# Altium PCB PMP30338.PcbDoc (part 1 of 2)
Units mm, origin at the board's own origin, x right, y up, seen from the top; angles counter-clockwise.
Board outline 50.04 x 70.1 mm, 4 copper layers (Top Layer, GND, Signal Layer, Bottom Layer), stack 2.028 mm thick; 61 components, 55 nets, 302 pads, 122 vias.
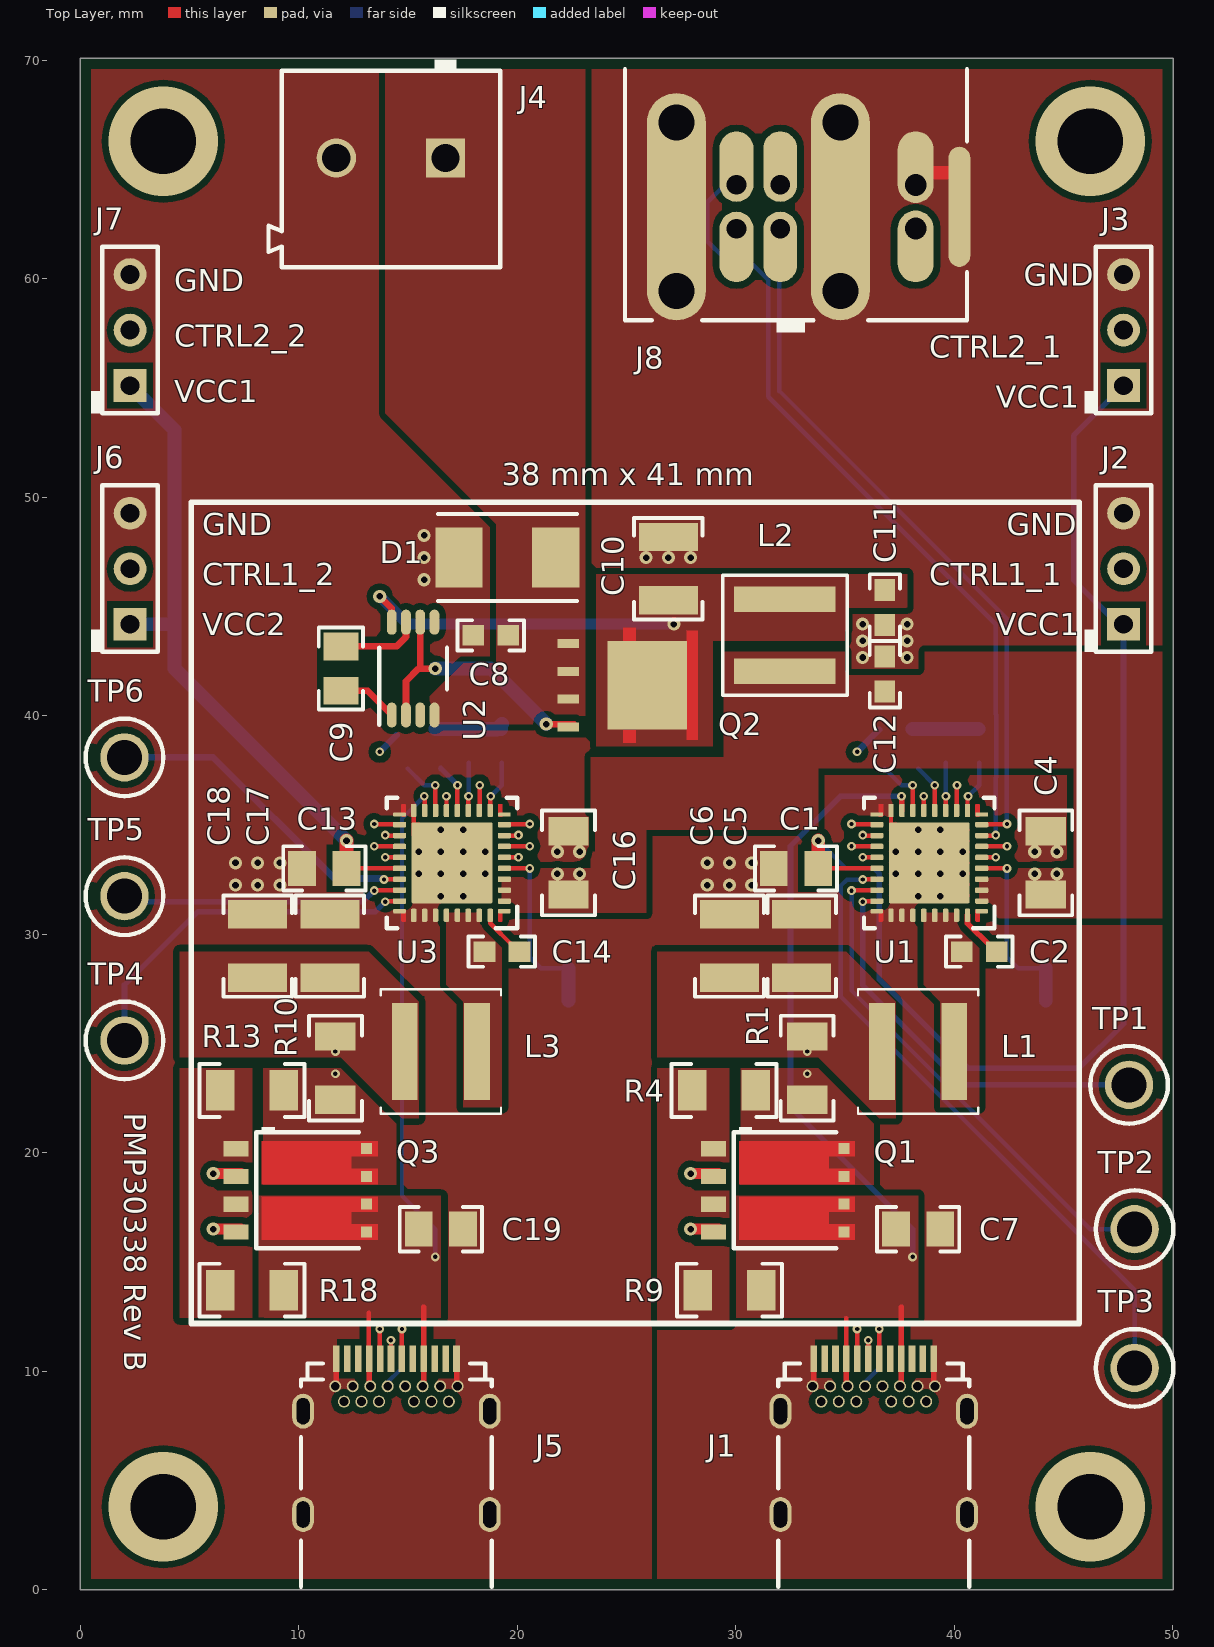
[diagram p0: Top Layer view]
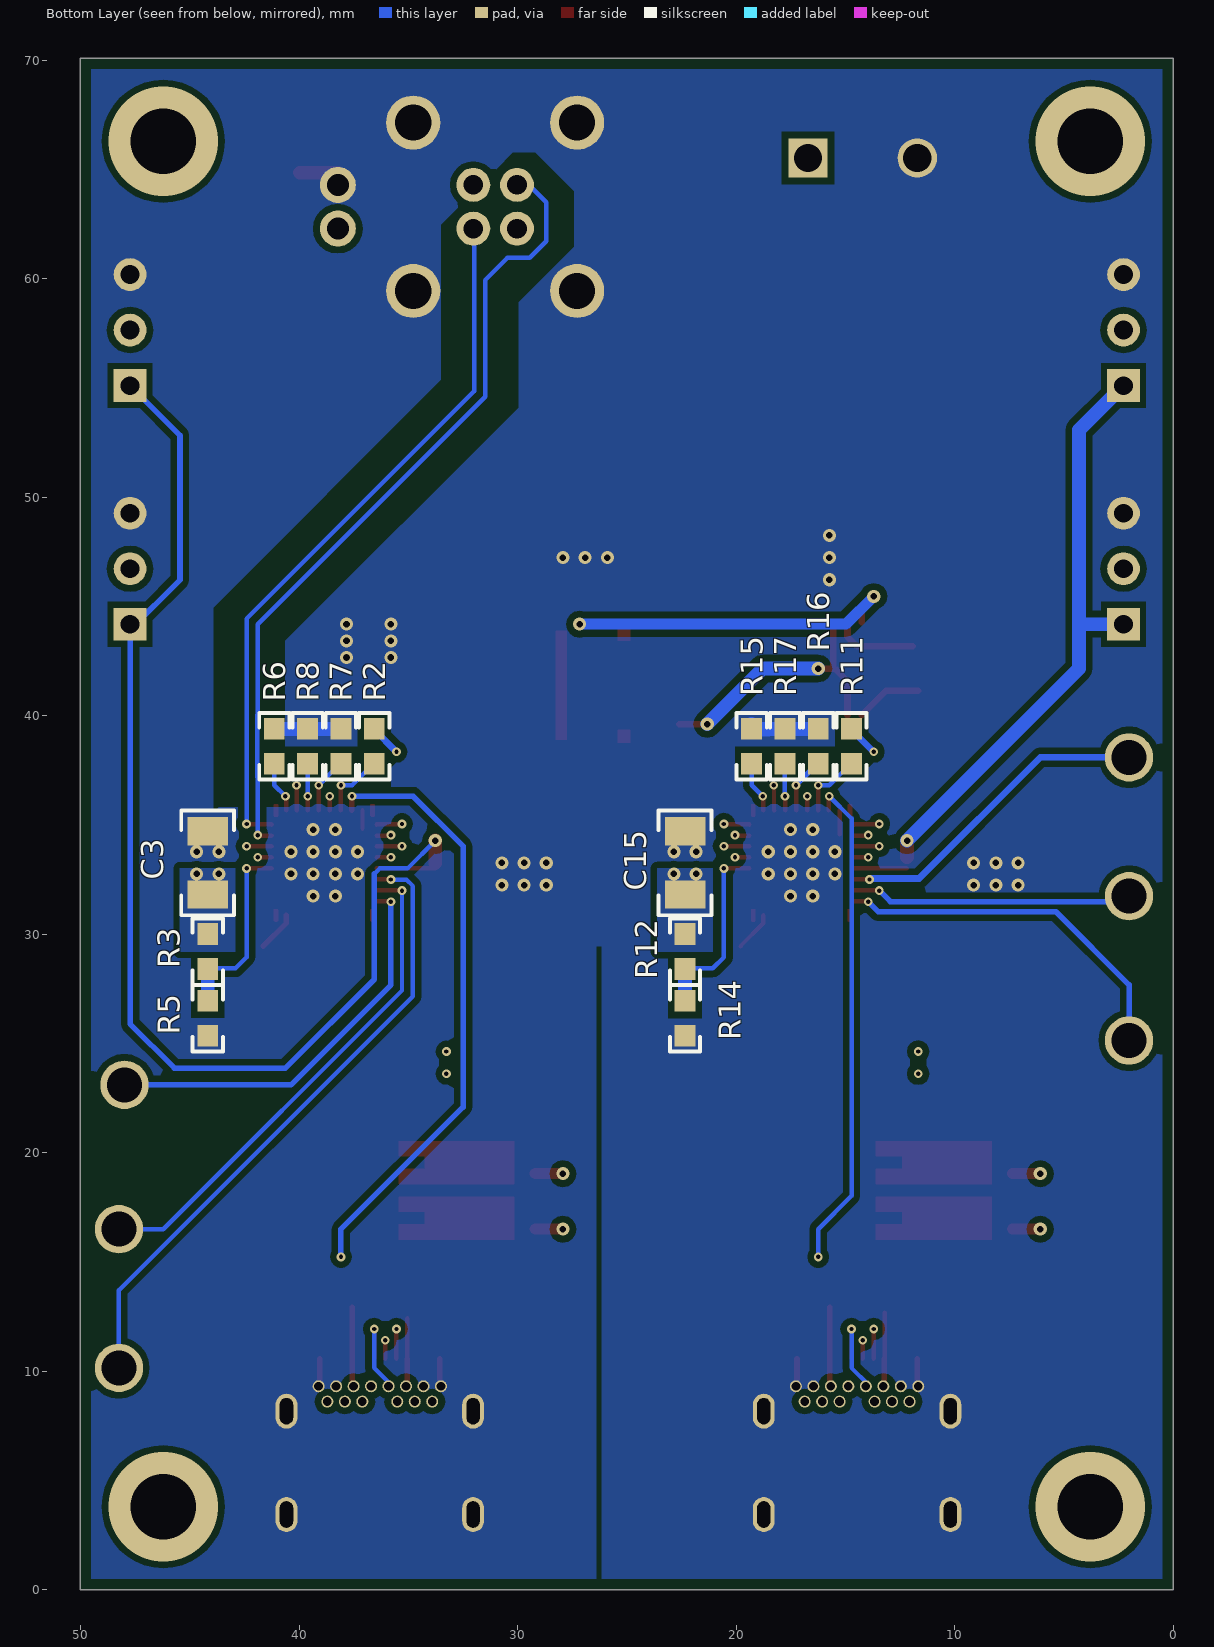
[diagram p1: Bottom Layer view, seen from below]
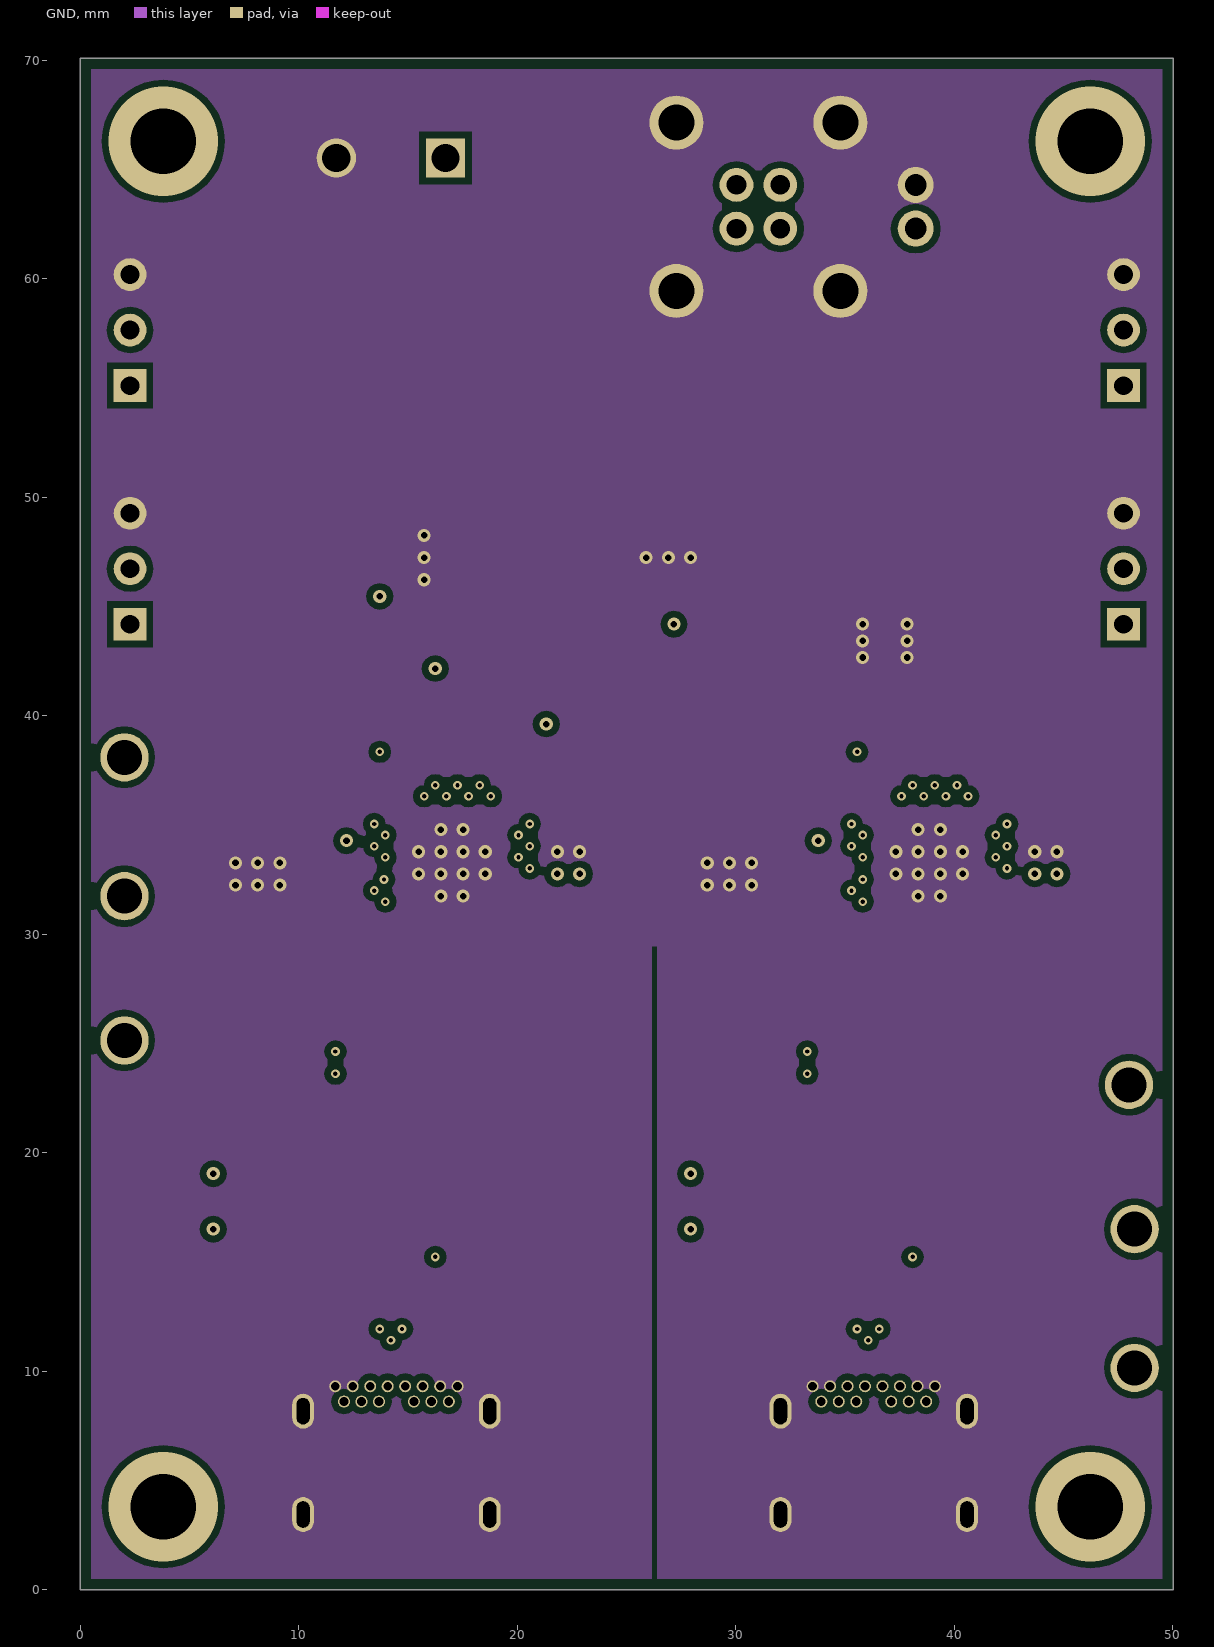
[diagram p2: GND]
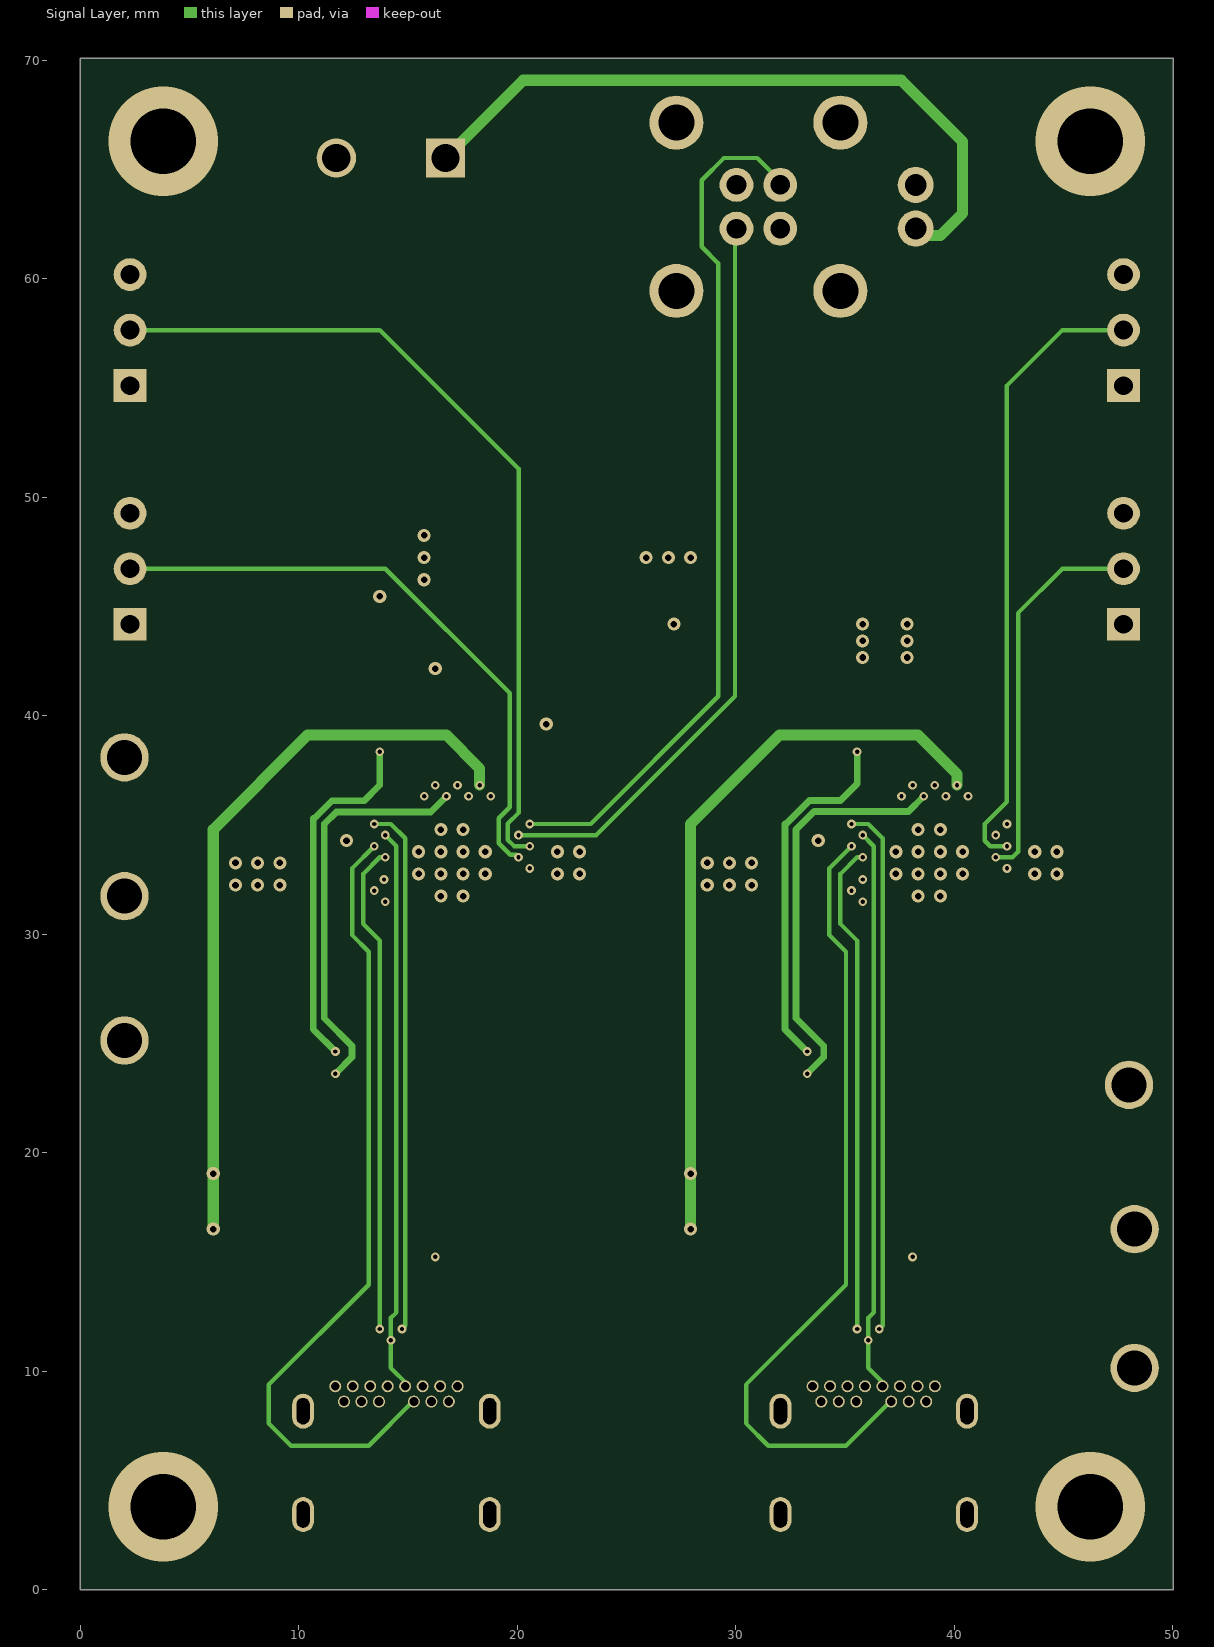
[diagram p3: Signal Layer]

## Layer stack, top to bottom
Top Solder: solder mask 0.0102, Solder Resist, Dk 3.5
Top Layer: signal copper 0.0356
Dielectric1: core 1.5037, FR-4, Dk 4.8
GND: signal copper 0.036
Dielectric 3: prepreg 0.127, Dk 4.2
Signal Layer: signal copper 0.036
Dielectric 2: core 0.254, Dk 4.2
Bottom Layer: signal copper 0.0356
Bottom Solder: solder mask 0.0102, Solder Resist, Dk 3.5

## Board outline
0,0 0,70.104 50.038,70.104 50.038,0

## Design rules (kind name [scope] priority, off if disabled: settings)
AcuteAngle [All] p1: minimum=4.50000000000000E+0001 checktracksonly=FALSE
AssemblyTestPointUsage [All] p1: valid=2
Clearance Clearance_Keepouts [((IsTrack Or IsArc) And Not InPoly) And IsFree and IsKeepOut vs ((IsTrack Or IsArc) And Not InPoly) And IsFree and IsKeepOut] p1: gap=0 ignorepadtopadclearanceinfootprint=FALSE
Clearance Clearance_BoardEdge_MountingHoles [OnCopper and InComponentClass('Mounting Holes') vs IsKeepOut] p2: gap=1.016 ignorepadtopadclearanceinfootprint=FALSE except(0: Arc-Hole Track-Hole SMDPad-Hole THPad-Hole Via-Hole Fill-Hole Poly-Hole Region-Hole Text-Hole)
Clearance Clearance_BoardEdge_Poly [OnCopper and InPoly vs IsKeepOut] p3: gap=0.635 ignorepadtopadclearanceinfootprint=FALSE except(0: Arc-Hole Track-Hole SMDPad-Hole THPad-Hole Via-Hole Fill-Hole Poly-Hole Region-Hole Text-Hole)
Clearance Clearance_BoardEdge [OnCopper and Not InComponentClass('Logo') and not InComponentClass('FiducialMark') and not InRegion(1000,500,4000,800) and Not IsKeepout vs IsKeepOut] p4: gap=1.905 ignorepadtopadclearanceinfootprint=FALSE except(0: Arc-Hole Track-Hole SMDPad-Hole THPad-Hole Via-Hole Fill-Hole Poly-Hole Region-Hole Text-Hole)
Clearance Clearance_Poly [InPolygon] p5: gap=0.3 ignorepadtopadclearanceinfootprint=FALSE
Clearance [All] p6: gap=0.2 ignorepadtopadclearanceinfootprint=FALSE except(0: Arc-Hole Track-Hole SMDPad-Hole THPad-Hole Via-Hole Fill-Hole Poly-Hole Region-Hole Text-Hole)
ComponentClearance ComponentClearance_MountingHoles_FiducialMarks [InComponentClass('Mounting Holes') vs InComponentClass('FiducialMark')] p1: gap=1.27 collisioncheckmode=3 verticalgap=0.254 showdistances=FALSE
ComponentClearance ComponentClearance_Shunt [InComponentClass('Header') vs InComponentClass('Shunt')] p2: gap=0 collisioncheckmode=3 verticalgap=0 showdistances=FALSE
ComponentClearance ComponentClearance_Logo [InComponentClass('Logo')] p3: gap=1.27 collisioncheckmode=3 verticalgap=0.254 showdistances=FALSE
ComponentClearance ComponentClearance_ScrewToNut [(HasFootprint('NY PMS 440 0025 PH')) vs (HasFootprint('Keystone_1902C'))] p4: gap=0.127 collisioncheckmode=3 verticalgap=0.254 showdistances=FALSE
ComponentClearance ComponentClearance_MountingHoles [InComponentClass('Mounting Holes')] p5: gap=6.35 collisioncheckmode=3 verticalgap=2540 showdistances=FALSE
ComponentClearance ComponentClearance_SmallPassives [HasFootprint('0201*') or HasFootprint('0402*') or HasFootprint('0508') or HasFootprint('0603*') or HasFootprint('0612') or HasFootprint('0805*') or HasFootprint('0815*') or HasFootprint('0830*') or HasFootprint('1206*') or HasFootprint('1210*') or HasFootprint('1808*') or HasFootprint('1812*') or HasFootprint('1825*') or HasFootprint('2010*') or HasFootprint('2220*') or HasFootprint('2225*') or HasFootprint('2512*') or HasFootprint('2728*') or HasFootprint('3518*') vs HasFootprint('0201*') or HasFootprint('0402*') or HasFootprint('0508') or HasFootprint('0603*') or HasFootprint('0612') or HasFootprint('0805*') or HasFootprint('0815*') or HasFootprint('0830*') or HasFootprint('1206*') or HasFootprint('1210*') or HasFootprint('1808*') or HasFootprint('1812*') or HasFootprint('1825*') or HasFootprint('2010*') or HasFootprint('2220*') or HasFootprint('2225*') or HasFootprint('2512*') or HasFootprint('2728*') or HasFootprint('3518*')] p6: gap=0.508 collisioncheckmode=3 verticalgap=0.254 showdistances=FALSE
ComponentClearance ComponentClearance_THtoSMT [IsThruComponent vs IsSMTComponent] p7: gap=2.54 collisioncheckmode=3 verticalgap=0.762 showdistances=FALSE
ComponentClearance ComponentClearance_THtoTH [IsThruComponent vs IsThruComponent] p8: gap=3 collisioncheckmode=3 verticalgap=0.762 showdistances=FALSE
ComponentClearance [All] p9: gap=1.016 collisioncheckmode=3 verticalgap=0.254 showdistances=FALSE
DiffPairsRouting [All] p1: maxlimit=2.54 minlimit=0.254 mostfreqgap=0.254 toplayer_minwidth=0.381 toplayer_maxwidth=0.381 toplayer_prefwidth=0.381 midlayer1_minwidth=0.381 midlayer1_maxwidth=0.381 midlayer1_prefwidth=0.381 midlayer2_minwidth=0.381 midlayer2_maxwidth=0.381 midlayer2_prefwidth=0.381 bottomlayer_minwidth=0.381 bottomlayer_maxwidth=0.381 bottomlayer_prefwidth=0.381 maxuncoupledlength=25.4
FabricationTestPointUsage TestPointUsage [All] p1: valid=2 allowmultiple=FALSE
FabricationTestpoint Testpoint [All] p1: side=3 testpointundercomponent=TRUE minsize=1.016 maxsize=2.54 preferedsize=1.524 minholesize=0 maxholesize=1.016 preferedholesize=0.813 testpointgrid=0.025 allowsidetop=TRUE allowsidebottom=TRUE usegrid=TRUE gridtolerance=0
FanoutControl Fanout_LCC [IsLCC] p1: bgadir=Out bgaviamode=Centered fanoutstyle=Auto fanoutdirection=Alternating viagrid=0.025 // Fanout_LCC (Default Rule)
FanoutControl Fanout_BGA [IsBGA] p2: bgadir=Out bgaviamode=Centered fanoutstyle=Auto fanoutdirection=Alternating viagrid=0.025 // Fanout_BGA (Default Rule)
FanoutControl Fanout_Default [All] p4: bgadir=Out bgaviamode=Centered fanoutstyle=Auto fanoutdirection=Alternating viagrid=0.025 // Fanout_Default (Default Rule)
FanoutControl Fanout_Small [(CompPinCount < 5)] p5: bgadir=Out bgaviamode=Centered fanoutstyle=Auto fanoutdirection=OutThenIn viagrid=0.025 // Fanout_Small (Default Rule)
HoleSize [All] p1: absolutevalues=TRUE maxlimit=6.375 minlimit=0.3 maxpercent=80.000 minpercent=20.000
MinimumAnnularRing MinimumAnnularRing_ThermalPadVias [IsVia and InAnyComponent] p1: minimumring=0.15
MinimumAnnularRing [All] p2: minimumring=0.229
MinimumSolderMaskSliver MinimumSolderMaskSliver_Logo [InComponentClass('Logo') vs InComponentClass('Logo')] p1: minsoldermaskwidth=0.018
MinimumSolderMaskSliver [All] p2: minsoldermaskwidth=0.1
PlaneConnect [All] p1: planeconnectstyle=Relief reliefexpansion=0.254 reliefentries=4 reliefconductorwidth=0.254 reliefairgap=0.254
PolygonConnect [All] p1: connectstyle=Direct reliefconductorwidth=0.254 reliefentries=4 polygonreliefangle="90 Angle" airgapwidth=0.254
RoutingVias ThermalPadVias [IsVia and InAnyComponent] p1: holewidth=0.2 width=0.5 viastyle="Through Hole" minholewidth=0.3 minwidth=0.6 maxholewidth=0.33 maxwidth=0.8
RoutingVias [All] p2: holewidth=0.406 width=0.864 viastyle="Through Hole" minholewidth=0.3 minwidth=0.6 maxholewidth=1.016 maxwidth=1.651
SilkToBoardRegionClearance [Not ((IsComment or IsDesignator) And (Hide <> 'False')) and not InRegion(1000,500,4000,800)] p1:
SilkToSilkClearance SilkToSilkClearance_Pb-FreeLogo [(HasFootprint('Pb-Free_Overlay_Medium') OR HasFootprint('Pb-Free_Overlay_Small')) vs (HasFootprint('Pb-Free_Overlay_Medium') OR HasFootprint('Pb-Free_Overlay_Small'))] p1: silktosilkclearance=0
SilkToSilkClearance [All] p2: silktosilkclearance=0.102
SilkToSolderMaskClearance SilkToComonentPadClearance [IsPad and InAnycomponent] p1: minsilkscreentomaskgap=0.127 clearancetoexposedcopper=TRUE
SilkToSolderMaskClearance "Silk to Solder Mask Opening" [All] p2: minsilkscreentomaskgap=0.102 clearancetoexposedcopper=FALSE
SolderMaskExpansion [All] p1: expansion=0.05
Width [All] p1: maxlimit=2.54 minlimit=0.152 preferedwidth=0.254 checkconnectedcopper=TRUE
15 further rules are at their usual default settings.

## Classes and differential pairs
component class Header: J2 J3 J6 J7

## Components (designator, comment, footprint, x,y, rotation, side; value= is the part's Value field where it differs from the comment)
C1 "GRM21BR71C105MA01L" 0805_HV 32.766,33.02 r180 top value=1uF
C2 "GRM188R71C474KA88D" 0603 41.148,29.21 r0 top value=0.47uF
C3 "GRM319R61H475KA12" 1206 44.196,33.274 r90 bottom value=4.7uF
C4 "GRM319R61H475KA12" 1206 44.196,33.274 r90 top value=4.7uF
C5 "GRM32ER71A226ME20L" 1210_270 33.02,29.464 r90 top value=22uF
C6 "GRM32ER71A226ME20L" 1210_270 29.718,29.464 r90 top value=22uF
C7 "GRM21BR71A106ME51L" 0805_HV 38.354,16.51 r0 top value=10uF
C8 "GRM188R71H104KA93D" 0603 18.796,43.688 r180 top value=0.1uF
C9 "GRM219R71C225KE15" 0805_HV 11.938,42.164 r270 top value=2.2uF
C10 "GRM32ER71H106MA12" 1210_270 26.924,46.736 r90 top value=10uF
C11 "GRM188R71H104KA93D" 0603 36.83,44.958 r270 top value=0.1uF
C12 "GRM188R71H104KA93D" 0603 36.83,41.91 r90 top value=0.1uF
C13 "GRM21BR71C105MA01L" 0805_HV 11.176,33.02 r180 top value=1uF
C14 "GRM188R71C474KA88D" 0603 19.304,29.21 r0 top value=0.47uF
C15 "GRM319R61H475KA12" 1206 22.352,33.274 r90 bottom value=4.7uF
C16 "GRM319R61H475KA12" 1206 22.352,33.274 r90 top value=4.7uF
C17 "GRM32ER71A226ME20L" 1210_270 11.43,29.464 r90 top value=22uF
C18 "GRM32ER71A226ME20L" 1210_270 8.128,29.464 r90 top value=22uF
C19 "GRM21BR71A106ME51L" 0805_HV 16.51,16.51 r0 top value=10uF
D1 "SM6T42CAY" SMB-Bi 19.558,47.244 r0 top value=36V
J1 "632723300011" Wurth_632_723_300_011 36.322,0 r0 top
J2 "800-10-003-10-001000" Mill-Max_800-10-003-10-001000 47.752,46.736 r90 top
J3 "800-10-003-10-001000" Mill-Max_800-10-003-10-001000 47.752,57.658 r90 top
J4 "691 101 710 002" Wurth_691101710002 14.224,65.532 r180 top
J5 "632723300011" Wurth_632_723_300_011 14.478,0 r0 top
J6 "800-10-003-10-001000" Mill-Max_800-10-003-10-001000 2.286,46.736 r90 top
J7 "800-10-003-10-001000" Mill-Max_800-10-003-10-001000 2.286,57.658 r90 top
J8 "99S20D-40MA5-D" Rosenberger_99S20D-40MA5-D 32.766,69.85 r0 top
L1 "XAL5050-103MEB" XAL5050 38.354,24.638 r180 top value=10uH
L2 "XAL5030-122MEB" XAL5030 32.258,43.688 r270 top value=1.2uH
L3 "XAL5050-103MEB" XAL5050 16.51,24.638 r180 top value=10uH
Q1 "BUK9K18-40E,115" SOT1205 32.258,18.288 r0 top value=40V
Q2 "SQJ412EP-T1-GE3" PowerPAK_SO-8L 25.146,41.402 r0 top value=40V
Q3 "BUK9K18-40E,115" SOT1205 10.414,18.288 r0 top value=40V
R1 "CSR1206FK15L0" 1206 33.274,23.876 r270 top value=0.015
R2 "CRCW0603300RJNEA" 0603 36.574,38.608 r90 bottom value=300
R3 "CRCW0603100KFKEA" 0603 44.196,29.21 r90 bottom value=100k
R4 "RC1206JR-070RL" 1206 29.464,22.86 r0 top value=0
R5 "CRCW060324K9FKEA" 0603 44.196,26.162 r90 bottom value=24.9k
R6 "CRCW060349K9FKEA" 0603 41.15,38.608 r270 bottom value=49.9k
R7 "CRCW060313K0FKEA" 0603 38.102,38.608 r270 bottom value=13.0k
R8 "CRCW060313K0FKEA" 0603 39.626,38.608 r270 bottom value=13.0k
R9 "RC1206JR-070RL" 1206 29.718,13.716 r180 top value=0
R10 "CSR1206FK15L0" 1206 11.684,23.876 r270 top value=0.015
R11 "CRCW0603300RJNEA" 0603 14.73,38.608 r90 bottom value=300
R12 "CRCW0603100KFKEA" 0603 22.352,29.21 r90 bottom value=100k
R13 "RC1206JR-070RL" 1206 7.874,22.86 r0 top value=0
R14 "CRCW060324K9FKEA" 0603 22.352,26.162 r90 bottom value=24.9k
R15 "CRCW060349K9FKEA" 0603 19.306,38.608 r270 bottom value=49.9k
R16 "CRCW060313K0FKEA" 0603 16.258,38.608 r270 bottom value=13.0k
R17 "CRCW060313K0FKEA" 0603 17.782,38.608 r270 bottom value=13.0k
R18 "RC1206JR-070RL" 1206 7.874,13.716 r180 top value=0
TP1 "5012" Keystone5012 48.006,23.114 r90 top
TP2 "5012" Keystone5012 48.26,16.51 r90 top
TP3 "5012" Keystone5012 48.26,10.16 r90 top
TP4 "5012" Keystone5012 2.032,25.146 r90 top
TP5 "5012" Keystone5012 2.032,31.75 r90 top
TP6 "5012" Keystone5012 2.032,38.1 r90 top
U1 "TPS25830S10QWRHB" RHB0032R 38.862,33.274 r180 top
U2 "LM74610QDGKRQ1" DGK0008A_L 15.24,42.164 r90 top
U3 "TPS25830S10QWRHB" RHB0032R 17.018,33.274 r180 top

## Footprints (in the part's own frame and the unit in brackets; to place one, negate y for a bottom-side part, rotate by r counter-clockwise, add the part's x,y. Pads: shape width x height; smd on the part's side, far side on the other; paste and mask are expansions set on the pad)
0603 [mm] "0603 from SM-752 data"
  rect 1x0.95 smd: 1(-0.8,0) 2(0.8,0)
  silkscreen extent -1.52,-0.69 1.52,0.69, body extent -0.87,-0.47 0.87,0.47, height 1
0805_HV [mil] "0805 with 30mil clearance between pads"
  rect 50x63 smd: 1(-40,0) 2(40,0)
  silkscreen extent -74,-40 74,40, body extent -43,-29 43,29, height 57
1206 [mm] "1206 from SM-752 data"
  rect 1.3x1.85 smd: 1(-1.45,0) 2(1.45,0)
  silkscreen extent -2.4,-1.21 2.4,1.21, body extent -1.7,-0.9 1.7,0.9, height 1.35
1210_270 [mm] "1210"
  rect 1.3x2.7 smd: 1(-1.45,0) 2(1.45,0)
  silkscreen extent -2.32,-1.57 2.32,1.57, body extent -1.7,-1.35 1.7,1.35, height 2.7
DGK0008A_L [mm] "TSOP, 8-Leads, Body 3x3mm, Pitch 0.65mm, IPC High Density"
  oval 1.15x0.45 smd: 1(-2.125,0.975) 2(-2.125,0.325) 3(-2.125,-0.325) 4(-2.125,-0.975) 5(2.125,-0.975) 6(2.125,-0.325) 7(2.125,0.325) 8(2.125,0.975)
  silkscreen extent -2.58,-1.55 0.95,1.55, body extent -2.45,-1.5 2.45,1.5, height 0.96
Keystone5012 [mil] "Keystone Multipurpose loops"
  round 87 hole 63: 1(0,0)
  silkscreen extent -70,-70 70,70, body extent -63,-63 63,62, height 319
Mill-Max_800-10-003-10-001000 [mm] "Mill-Max"
  rect 1.5x1.5 hole 0.85: 1(-2.54,0)
  round 1.5 hole 0.85: 2(0,0) 3(2.54,0)
  silkscreen extent -3.81,-1.27 3.81,1.78, body extent -3.81,-1.27 3.81,1.27, height 8.13
PowerPAK_SO-8L [mm] "based on Vishay recommended land pattern Document 63818 Feb 7, 2012"
  rect 1x0.41 smd: 1(-2.805,1.905) 2(-2.805,0.635) 3(-2.805,-0.635) 4(-2.805,-1.905)
  rect 3.63x4.061 smd: 5(0.805,0)
  Top Layer region: 2.615,-2.5 3.125,-2.5 3.125,2.5 2.615,2.5
  Top Layer region: -0.297,2.03 0.298,2.03 0.298,2.64 -0.297,2.64
  Top Layer region: -0.298,-2.64 0.298,-2.64 0.298,-2.03 -0.298,-2.03
  body extent -3.07,-2.57 3.08,2.57, height 1.21
RHB0032R [mm] "QFN, 32-Leads, Body 5x5mm, Pitch 0.5mm, Thermal Pad 3.7x3.7mm"
  rrect40% 0.6x0.25 smd: 1(-2.4,1.75) 2(-2.4,1.25) 3(-2.4,0.75) 4(-2.4,0.25) 5(-2.4,-0.25) 6(-2.4,-0.75) 7(-2.4,-1.25) 8(-2.4,-1.75) 17(2.4,-1.75) 18(2.4,-1.25) 19(2.4,-0.75) 20(2.4,-0.25) 21(2.4,0.25) 22(2.4,0.75) 23(2.4,1.25) 24(2.4,1.75)
  rrect40% 0.25x0.6 smd: 9(-1.75,-2.4) 10(-1.25,-2.4) 11(-0.75,-2.4) 12(-0.25,-2.4) 13(0.25,-2.4) 14(0.75,-2.4) 15(1.25,-2.4) 16(1.75,-2.4) 25(1.75,2.4) 26(1.25,2.4) 27(0.75,2.4) 28(0.25,2.4) 29(-0.25,2.4) 30(-0.75,2.4) 31(-1.25,2.4) 32(-1.75,2.4)
  rrect9% 1.06x1.06 on Top Paste: 33(-1.26,1.26) 33(-1.26,0) 33(-1.26,-1.26) 33(0,1.26) 33(0,0) 33(0,-1.26) 33(1.26,1.26) 33(1.26,0) 33(1.26,-1.26)
  rrect3% 3.7x3.7 smd paste-2: 33(0,0)
  rrect50% 0.575x0.2 smd: A1(-2.4,2.213) A2(-2.4,-2.213) A3(2.4,-2.213) A4(2.4,2.213)
  Top Layer region: 2.113,-2.638 2.113,-2.163 2.116,-2.143 2.127,-2.127 2.143,-2.116 2.163,-2.113 2.163,-2.113 2.262,-2.113 2.282,-2.116 2.298,-2.127 2.309,-2.143 2.312,-2.163 2.312,-2.163 2.312,-2.638 2.309,-2.657 2.298,-2.673 2.282,-2.684 2.262,-2.688 2.262,-2.688 2.163,-2.688 2.143,-2.684 2.127,-2.673 2.116,-2.657 2.113,-2.638
  Top Layer region: -2.113,-2.638 -2.113,-2.163 -2.116,-2.143 -2.127,-2.127 -2.143,-2.116 -2.163,-2.113 -2.163,-2.113 -2.262,-2.113 -2.282,-2.116 -2.298,-2.127 -2.309,-2.143 -2.312,-2.163 -2.312,-2.163 -2.312,-2.638 -2.309,-2.657 -2.298,-2.673 -2.282,-2.684 -2.262,-2.688 -2.262,-2.688 -2.163,-2.688 -2.143,-2.684 -2.127,-2.673 -2.116,-2.657 -2.113,-2.638
  Top Layer region: -2.113,2.638 -2.113,2.163 -2.116,2.143 -2.127,2.127 -2.143,2.116 -2.163,2.113 -2.163,2.113 -2.262,2.113 -2.282,2.116 -2.298,2.127 -2.309,2.143 -2.312,2.163 -2.312,2.163 -2.312,2.638 -2.309,2.657 -2.298,2.673 -2.282,2.684 -2.262,2.688 -2.262,2.688 -2.163,2.688 -2.143,2.684 -2.127,2.673 -2.116,2.657 -2.113,2.638
  Top Layer region: 2.113,2.638 2.113,2.163 2.116,2.143 2.127,2.127 2.143,2.116 2.163,2.113 2.163,2.113 2.262,2.113 2.282,2.116 2.298,2.127 2.309,2.143 2.312,2.163 2.312,2.163 2.312,2.638 2.309,2.657 2.298,2.673 2.282,2.684 2.262,2.688 2.262,2.688 2.163,2.688 2.143,2.684 2.127,2.673 2.116,2.657 2.113,2.638
  silkscreen extent -2.99,-2.99 2.99,2.99, body extent -2.5,-2.5 2.5,2.5, height 1
Rosenberger_99S20D-40MA5-D [mm] "Right Angle Plug for PCB, 6-Lead, TH"
  round 1.55 hole 0.9: 1(-0.725,-7.55) 2(-0.725,-5.55) 3(-2.725,-5.55) 4(-2.725,-7.55)
  round 1.65 hole 1: 5(5.475,-7.55) 6(5.475,-5.55)
  oval 2.7x10.4 smd: S1(-5.475,-6.55) S2(2.025,-6.55)
  oval 1x5.5 smd: S3(7.475,-6.55)
  round 2.475 hole 1.65: ""(-5.475,-10.4) ""(-5.475,-2.7) ""(2.025,-10.4) ""(2.025,-2.7)
  oval 1.55x3.225 smd: ""(-2.725,-8.387) ""(-2.725,-4.713) ""(-0.725,-8.387) ""(-0.725,-4.713)
  oval 1.65x3.275 smd: ""(5.475,-8.362) ""(5.475,-4.738)
  silkscreen extent -7.82,-12.3 7.83,-0.25, body extent -7.82,-11.75 7.83,15.7, height 14.15
SMB-Bi [mm] "Molded Diode, 2-Leads, Body 5.4x3.6mm, IPC Medium Density, based on OnSemi component dimensions"
  rect 2.159x2.743 smd: 1(-2.21,0) 2(2.21,0)
  silkscreen extent -3.17,-1.99 3.17,1.99, body extent -2.65,-1.85 2.65,1.85, height 2.26
SOT1205 [mm] "SMD, 8-Leads, Body 4.575x5.125mm, Pitch 1.27mm"
  rect 1.15x0.7 smd paste-0.025 mask+0.062: 1(-3.275,1.905) 2(-3.275,0.635) 3(-3.275,-0.635) 4(-3.275,-1.905)
  rect 0.5x0.5 smd: 5(2.7,-1.905) 6(2.7,-0.635) 7(2.7,0.635) 8(2.7,1.905)
  Top Layer region: -2.1,2.255 3.2,2.255 3.2,1.555 2,1.555 2,0.985 3.2,0.985 3.2,0.285 -2.1,0.285
  Top Layer region: -2.1,-2.255 3.2,-2.255 3.2,-1.555 2,-1.555 2,-0.985 3.2,-0.985 3.2,-0.285 -2.1,-0.285
  silkscreen extent -2.35,-2.65 2.35,2.9, body extent -3.7,-2.65 2.9,2.65, height 1.06
Wurth_632_723_300_011 [mm] "Connector, Receptacle, USB Type C, R/A"
  rect 0.3x1.2 smd: A1(-2.75,10.58) A2(-2.25,10.58) A3(-1.75,10.58) A4(-1.25,10.58) A5(-0.75,10.58) A6(-0.25,10.58) A7(0.25,10.58) A8(0.75,10.58) A9(1.25,10.58) A10(1.75,10.58) A11(2.25,10.58) A12(2.75,10.58)
  round 0.55 hole 0.4: B1(2.8,9.32) B2(2.4,8.62) B3(1.6,8.62) B4(1.2,9.32) B5(0.8,8.62) B6(0.4,9.32) B7(-0.4,9.32) B8(-0.8,8.62) B9(-1.2,9.32) B10(-1.6,8.62) B11(-2.4,8.62) B12(-2.8,9.32) M1(2,9.32) M2(-2,9.32)
  rrect100% 1x1.6 hole 0.6 slot 1.2 at 90 deg: S1(-4.27,8.18) S2(-4.27,3.45) S3(4.27,3.45) S4(4.27,8.18)
  silkscreen extent -4.37,0.15 4.37,10.36, body extent -4.37,-0.96 4.37,10.83, height 3.07
Wurth_691101710002 [mm] "Terminal Block, 5 mm, 2x1, TH"
  rect 1.8x1.8 hole 1.3: 1(-2.5,0)
  round 1.8 hole 1.3: 2(2.5,0)
  silkscreen extent -5,-4.5 5.6,5, body extent -5.6,-4 5.6,5, height 12.5
XAL5030 [mil] "Coilcraft XAL5030 12/12/11"
  rect 46x183 smd: 1(-65,0) 2(65,0)
  silkscreen extent -108,-112 108,112, body extent -108,-112 108,112, height 122
XAL5050 [mm] "CoilCraft XAL5050 5.28 x 5.48 x 5.1 mm"
  rect 1.18x4.44 smd: 1(-1.655,0) 2(1.655,0)
  silkscreen extent -2.75,-2.85 2.75,2.85, body extent -2.74,-2.84 2.74,2.84, height 5.1

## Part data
C1 C13: library part CMP-0008324-2, "CAP, CERM, 1 uF, 16 V, +/- 20%, X7R, 0805", Cap_Case=0805, Manufacturer=MuRata, Supplier Part Number 1=490-1692-1-ND, TempCo=X7R, Tolerance_%=20%, Value1="0.003 ohm", Value2=16V, ValueDisplayed=1uF
C2 C14: library part CMP-0007398-2, "CAP, CERM, 0.47 uF, 16 V, +/- 10%, X7R, 0603", Cap_Case=0603, Manufacturer=MuRata, Supplier Part Number 1=490-3295-1-ND, TempCo=X7R, Tolerance_%=10%, Value1=Unknown, Value2=16V, ValueDisplayed=0.47uF
C3 C4 C15 C16: library part CMP-0008865-2, "CAP, CERM, 4.7 uF, 50 V, +/- 10%, X5R, 1206", Cap_Case=1206, Manufacturer=MuRata, Supplier Part Number 1=13T1225, TempCo=X5R, Tolerance_%=10%, Value1=Unknown, Value2=50V, ValueDisplayed=4.7uF
C5 C6 C17 C18: library part CMP-0009219-2, "CAP, CERM, 22 uF, 10 V, +/- 10%, X7R, 1210", Cap_Case=1210, Manufacturer=MuRata, Supplier Part Number 1=490-11653-1-ND, TempCo=X7R, Tolerance_%=10%, Value1="0.002 ohm", Value2=10V, ValueDisplayed=22uF
C7 C19: library part CMP-0008316-2, "CAP, CERM, 10 uF, 10 V, +/- 20%, X7R, 0805", Cap_Case=0805, Manufacturer=MuRata, Supplier Part Number 1=490-8316-1-ND, TempCo=X7R, Tolerance_%=20%, Value1=Unknown, Value2=10V, ValueDisplayed=10uF
C8 C11 C12: library part CMP-0007434-2, "CAP, CERM, 0.1 uF, 50 V, +/- 10%, X7R, 0603", Cap_Case=0603, Manufacturer=MuRata, Supplier Part Number 1=490-1519-1-ND, TempCo=X7R, Tolerance_%=10%, Value1=Unknown, Value2=50V, ValueDisplayed=0.1uF
C9: library part CMP-0008211-2, "CAP, CERM, 2.2 uF, 16 V, +/- 10%, X7R, 0805", Cap_Case=0805, Manufacturer=MuRata, TempCo=X7R, Tolerance_%=10%, Value1=Unknown, Value2=16V, ValueDisplayed=2.2uF
C10: library part CMP-0009227-2, "CAP, CERM, 10 uF, 50 V, +/- 20%, X7R, 1210", Cap_Case=1210, Manufacturer=MuRata, Supplier Part Number 1=490-12775-1-ND, TempCo=X7R, Tolerance_%=20%, Value1=Unknown, Value2=50V, ValueDisplayed=10uF
D1: library part CMP-0006049-2, "Diode, TVS, Bi, 36 V, 76 Vc, AEC-Q101, SMB", Manufacturer=STMicroelectronics, Supplier Part Number 1=497-12193-1-ND, Value1=W
J1 J5: library part CMP-0080891-1, "Connector, Receptacle, USB Type C, R/A", Color=Black, Current_A=3A, Manufacturer="Wurth Elektronik", Supplier Part Number 1=732-9618-1-ND, Voltage_V=5V
J2 J3 J6 J7: library part CMP-0055086-1, "Header, 100mil, 3x1, TH", Manufacturer=Mill-Max, Supplier Part Number 1=ED7203-ND
J4: library part CMP-0054828-1, "Terminal Block, 5 mm, 2x1, Tin, TH", Manufacturer="Wurth Elektronik", Supplier Part Number 1=732-2026-ND
J8: library part CMP-0055816-1, "RF Coaxial Connector, Bordeaux, R/A, TH", Color=Bordeaux, Manufacturer=Rosenberger, Supplier Part Number 1=476-99S20D-40MA5-D, Voltage_V=100V
L1 L3: library part CMP-0061007-1, "Inductor, Shielded, Composite, 10 uH, 4.9 A, 0.05 ohm, SMD", Manufacturer=Coilcraft, Value1="0.05 ohm", Value2=4.9A, ValueDisplayed=10uH
L2: library part CMP-0060999-1, "Inductor, Shielded, Composite, 1.2 uH, 11.1 A, 0.01 ohm, SMD", Manufacturer=Coilcraft, Value1="0.01 ohm", Value2=11.1A, ValueDisplayed=1.2uH
Q1 Q3: library part CMP-0000698-2, "MOSFET, 2-CH, N-CH, 40 V, 30 A, AEC-Q101, SOT1205", Alternate Manufacturer=None, Manufacturer=Nexperia, Supplier Part Number 1=568-9899-1-ND, Value2="14.5 nC"
Q2: library part CMP-0000746-1, "MOSFET, N-CH, 40 V, 32 A, PowerPAK_SO-8L", Alternate Manufacturer=None, Manufacturer=Vishay-Siliconix, Supplier Part Number 1=SQJ412EP-T1-GE3CT-ND, Value1=0.005, Value2="80 nC"
R1 R10: library part CMP-0017258-2, "RES, 0.015, 1%, 0.5 W, 1206", Manufacturer="Stackpole Electronics Inc", Power_W=500mW, Supplier Part Number 1=CSR1206FK15L0CT-ND, TempCo="100 ppm/C", Tolerance_%=1%, Value2=0.5W, Value_Code=R015, ValueDisplayed=0.015
R2 R11: library part CMP-0025781-2, "RES, 300, 5%, 0.1 W, 0603", Manufacturer=Vishay-Dale, Power_W=100mW, Supplier Part Number 1=541-300GCT-ND, TempCo="200 ppm/C", Tolerance_%=5%, Value2=0.1W, Value_Code=300R, ValueDisplayed=300
R3 R12: library part CMP-0021990-2, "RES, 100 k, 1%, 0.1 W, 0603", Manufacturer=Vishay-Dale, Power_W=100mW, Supplier Part Number 1=541-100KHCT-ND, TempCo="100 ppm/C", Tolerance_%=1%, Value2=0.1W, Value_Code=100k
R4 R9 R13 R18: library part CMP-0018759-2, "RES, 0, 5%, 0.25 W, 1206", Manufacturer="Yageo America", Power_W=250mW, Supplier Part Number 1=311-0.0ERCT-ND, TempCo="200 ppm/C", Tolerance_%=5%, Value2=0.25W, Value_Code=0000, ValueDisplayed=DNP
R5 R14: library part CMP-0022237-2, "RES, 24.9 k, 1%, 0.1 W, 0603", Manufacturer=Vishay-Dale, Power_W=100mW, Supplier Part Number 1=541-24.9KHCT-ND, TempCo="100 ppm/C", Tolerance_%=1%, Value2=0.1W, Value_Code=24k9, ValueDisplayed=24.9k
R6 R15: library part CMP-0022447-4, "RES, 49.9 k, 1%, 0.1 W, AEC-Q200 Grade 0, 0603", Manufacturer=Vishay-Dale, Power_W=100mW, Supplier Part Number 1=541-49.9KHCT-ND, TempCo="100 ppm/C", Tolerance_%=1%, Value2=0.1W, Value_Code=49k9, ValueDisplayed=49.9k
R7 R8 R16 R17: library part CMP-0022042-2, "RES, 13.0 k, 1%, 0.1 W, 0603", Manufacturer=Vishay-Dale, Power_W=100mW, Supplier Part Number 1=541-13.0KHCT-ND, TempCo="100 ppm/C", Tolerance_%=1%, Value2=0.1W, Value_Code=13k0, ValueDisplayed=13.0k
TP1 TP2 TP3 TP4 TP5 TP6: library part CMP-0055149-1, "Test Point, Multipurpose, White, TH", Color=White, Manufacturer=Keystone, Supplier Part Number 1=36-5012-ND
U1 U3: library part CMP-0074898-3, "USB Type-C and BC1.2 5V 3.5A Output, 36V Input Synchronous Buck with Cable Compensation, RHB0032R (VQFN-32)", Alternate Manufacturer="Texas Instruments"
U2: library part CMP-0076397-1, "Zero Iq Reverse Polarity Protection Smart Diode Controller, DGK0008A (VSSOP-8)", Alternate Manufacturer="Texas Instruments"

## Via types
v1: diameter 0.6, hole 0.3, Top Layer to Bottom Layer, 66 vias
v2: diameter 0.4, hole 0.2, Top Layer to Bottom Layer, 52 vias
v3: diameter 5, hole 3, Top Layer to Bottom Layer, 4 vias

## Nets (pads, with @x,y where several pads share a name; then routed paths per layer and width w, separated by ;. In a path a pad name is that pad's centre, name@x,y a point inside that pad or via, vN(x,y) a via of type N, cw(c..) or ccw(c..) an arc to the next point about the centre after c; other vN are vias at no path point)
CC1_1: J1.A5 U1.20 | length 24.5
  Top Layer w0.203: v2@35.566,11.932 35.566,10.586 J1.A5@35.572,10.58 ; v2@35.818,33.524 U1.20@36.462,33.524
  Signal Layer w0.203: v2(35.56,11.938) 35.56,29.718 34.798,30.48 34.798,32.766 35.56,33.528 v2(35.814,33.528)
CC1_2: J5.A5 U3.20 | length 24.5
  Top Layer w0.203: v2@13.722,11.932 13.722,10.586 J5.A5@13.728,10.58 ; v2@13.974,33.524 U3.20@14.618,33.524
  Signal Layer w0.203: v2(13.716,11.938) 13.716,29.718 12.954,30.48 12.954,32.766 13.716,33.528 v2(13.97,33.528)
CC2_1: J1.B5 U1.19 | length 38.1
  Top Layer w0.203: v2@35.312,34.03 36.462,34.03 U1.19@36.462,34.024
  Signal Layer w0.203: v2(35.306,34.036) 34.29,33.02 34.29,29.972 35.052,29.21 35.052,13.97 30.48,9.398 30.48,7.62 31.496,6.604 35.052,6.604 J1.B5@37.084,8.636
CC2_2: J5.B5 U3.19 | length 38.1
  Top Layer w0.203: v2@13.468,34.03 14.618,34.03 U3.19@14.618,34.024
  Signal Layer w0.203: v2(13.462,34.036) 12.446,33.02 12.446,29.972 13.208,29.21 13.208,13.97 8.636,9.398 8.636,7.62 9.652,6.604 13.208,6.604 J5.B5@15.24,8.636
CS+_1: C5.1 C6.1 L1.2 R1.1 R2.2 | length 17.8
  Signal Layer w0.305: v2(33.274,24.638) 32.258,25.654 32.258,35.052 32.306,35.052 33.382,36.128 34.798,36.128 35.56,36.89 v2(35.56,38.354)
  Bottom Layer w0.305: v2(35.56,38.354) R2.2@36.576,39.37
CS+_2: C17.1 C18.1 L3.2 R10.1 R11.2 | length 17.4
  Signal Layer w0.305: v2(11.684,24.638) 10.668,25.654 10.668,35.306 10.716,35.306 11.519,36.109 12.995,36.109 13.716,36.83 v2(13.716,38.354)
  Bottom Layer w0.305: v2(13.716,38.354) R11.2@14.478,39.116
CS-_1: Q1.7 Q1.8 R1.2 R4.2 U1.13 | length 19.1
  Top Layer w0.203: U1.13@38.612,35.674 v2@38.612,36.318
  Signal Layer w0.305: v2(33.274,23.622) 34.036,24.384 34.036,24.892 32.766,26.162 32.766,34.798 33.591,35.623 37.91,35.623 v2(38.608,36.322)
CS-_2: Q3.7 Q3.8 R10.2 R13.2 U3.13 | length 19
  Top Layer w0.203: U3.13@16.768,35.674 v2@16.768,36.318
  Signal Layer w0.305: v2(11.684,23.622) 12.446,24.384 12.446,24.892 11.176,26.162 11.176,35.052 11.728,35.604 16.046,35.604 v2(16.764,36.322)
CTRL1_1: J2.2 U1.5 | length 18.1
  Top Layer w0.203: U1.5@41.262,33.524 v2@41.906,33.524
  Signal Layer w0.203: v2(41.91,33.528) 42.672,33.528 42.926,33.782 42.926,44.704 44.958,46.736 J2.2@47.498,46.736
CTRL1_2: J6.2 U3.5 | length 28.7
  Top Layer w0.203: U3.5@19.418,33.524 v2@20.062,33.524
  Signal Layer w0.203: J6.2@2.286,46.99 2.54,46.736 13.97,46.736 19.663,41.043 19.663,35.814 19.161,35.312 19.161,34.169 19.691,33.639 19.955,33.639 v2(20.066,33.528)
CTRL2_1: J3.2 U1.6 | length 29.9
  Top Layer w0.203: U1.6@41.262,34.024 41.262,34.03 v2@42.412,34.03
  Signal Layer w0.203: v2(42.418,34.036) 41.656,34.036 41.402,34.29 41.402,35.052 42.418,36.068 42.418,55.118 44.958,57.658 J3.2@47.752,57.658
